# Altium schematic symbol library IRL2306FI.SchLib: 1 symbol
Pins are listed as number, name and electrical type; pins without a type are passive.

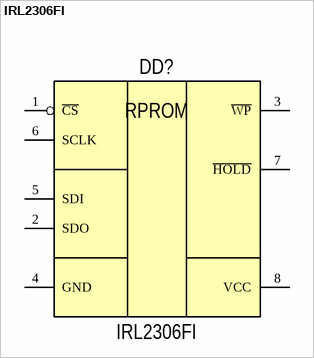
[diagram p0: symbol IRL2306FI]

## IRL2306FI
designator DD?
Микросхема ЭСППЗУ Flash-типа с последовательным интерфейсом SPI; TemperatureOperating: - 40°C to + 85°C
pins: 1 ~{CS}, 2 SDO, 3 ~{WP}, 4 GND, 5 SDI, 6 SCLK, 7 ~{HOLD}, 8 VCC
